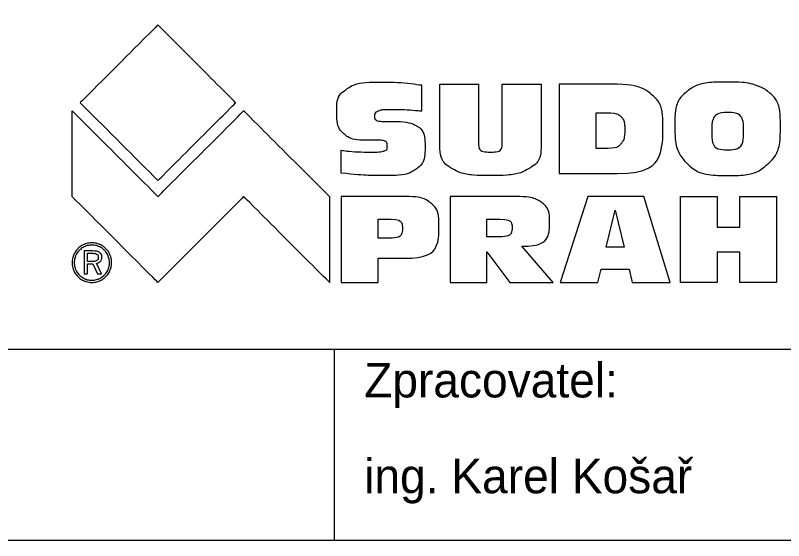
# Model space of a CAD drawing. Extents: x -78 to 132, y -2115 to -1818.
# Drawn here: x 60.19 to 102.29, y -2019.62 to -1990.83 of the extents above; entities that cross this region are included whole.
import ezdxf

# ---------------------------------------------------------------- set-up
doc = ezdxf.new("R2010")
doc.units = 0
for name, color, linetype in [('Rozpiska - logo SUDOP PRAHA', 7, 'Continuous'), ('Rozpiska_pole_6', 7, 'Continuous'), ('Rozpiska_pole_7', 7, 'Continuous')]:
    doc.layers.add(name, color=color, linetype=linetype)

msp = doc.modelspace()

# ---------------------------------------------------------------- linework, layer by layer
at = {"layer": 'Rozpiska - logo SUDOP PRAHA'}
for points in [[(92.81, -1994.604), (89.986, -1994.604), (89.986, -1999.495), (93.188, -1999.495)], [(92.634, -1998.124), (92.012, -1998.124), (92.012, -1996.176), (92.566, -1996.176)], [(81.559, -2000.764), (78.041, -2000.764), (78.041, -2005.467), (80.074, -2005.467), (80.074, -2004.146), (81.479, -2004.146)], [(87.592, -2000.764), (84.013, -2000.764), (84.013, -2005.467), (86.037, -2005.467), (86.037, -2003.8), (87.284, -2005.467), (89.656, -2005.467), (87.949, -2003.484)], [(92.109, -2005.467), (92.286, -2004.734), (93.824, -2004.734), (93.994, -2005.467), (96.076, -2005.467), (94.625, -2000.764), (91.565, -2000.764), (90.056, -2005.467), (92.109, -2005.467)], [(93.062, -2001.517), (93.552, -2003.539), (92.565, -2003.539), (93.062, -2001.517)], [(80.676, -2003.048), (80.074, -2003.048), (80.074, -2002.008), (80.778, -2002.008)], [(86.713, -2002.97), (86.037, -2002.97), (86.037, -2002.008), (86.738, -2002.008)], [(64.411, -2003.745), (63.954, -2003.745), (63.954, -2004.99), (64.142, -2004.99), (64.142, -2004.443), (64.433, -2004.443), (64.696, -2004.99), (64.91, -2004.99), (64.632, -2004.416)], [(64.375, -2004.319), (64.142, -2004.319), (64.142, -2003.872), (64.375, -2003.872)]]:
    msp.add_lwpolyline(points, dxfattribs=at)
for points in [[(63.739, -1995.621), (63.739, -1995.621), (68.001, -1991.359), (68.001, -1991.359), (68.001, -1991.359), (68.001, -1991.359), (72.263, -1995.621), (72.263, -1995.621), (72.263, -1995.621), (72.263, -1995.621), (68.001, -1999.883), (68.001, -1999.883), (68.001, -1999.883), (68.001, -1999.883), (63.739, -1995.621), (63.739, -1995.621)], [(78.041, -1999.475), (78.805, -1999.566), (79.608, -1999.612), (80.448, -1999.612), (80.448, -1999.612), (81.252, -1999.612), (81.819, -1999.494), (82.147, -1999.258), (82.147, -1999.258), (82.477, -1999.021), (82.642, -1998.613), (82.642, -1998.033), (82.642, -1998.033), (82.642, -1997.467), (82.494, -1997.088), (82.196, -1996.899), (82.196, -1996.899), (81.916, -1996.729), (81.347, -1996.644), (80.489, -1996.644), (80.489, -1996.644), (80.078, -1996.644), (79.872, -1996.548), (79.872, -1996.353), (79.872, -1996.353), (79.872, -1996.231), (79.933, -1996.142), (80.054, -1996.086), (80.054, -1996.086), (80.178, -1996.03), (80.393, -1996.002), (80.701, -1996.002), (80.701, -1996.002), (81.223, -1996.002), (81.796, -1996.032), (82.447, -1996.092), (82.447, -1996.092), (82.447, -1996.092), (82.447, -1994.65), (82.447, -1994.65), (82.447, -1994.65), (81.67, -1994.541), (80.943, -1994.486), (80.239, -1994.486), (80.239, -1994.486), (79.354, -1994.486), (78.726, -1994.612), (78.355, -1994.864), (78.355, -1994.864), (77.984, -1995.114), (77.799, -1995.514), (77.799, -1996.062), (77.799, -1996.062), (77.799, -1996.671), (77.931, -1997.093), (78.196, -1997.327), (78.196, -1997.327), (78.463, -1997.561), (78.907, -1997.676), (79.528, -1997.672), (79.528, -1997.672), (79.528, -1997.672), (80.046, -1997.672), (80.046, -1997.672), (80.046, -1997.672), (80.228, -1997.672), (80.361, -1997.692), (80.444, -1997.732), (80.444, -1997.732), (80.527, -1997.772), (80.569, -1997.859), (80.569, -1997.993), (80.569, -1997.993), (80.569, -1998.133), (80.514, -1998.224), (80.406, -1998.264), (80.406, -1998.264), (80.3, -1998.304), (80.121, -1998.324), (79.869, -1998.324), (79.869, -1998.324), (79.087, -1998.324), (78.477, -1998.29), (78.041, -1998.22), (78.041, -1998.22), (78.041, -1998.22), (78.041, -1999.475), (78.041, -1999.475)], [(83.449, -1997.93), (83.449, -1998.531), (83.669, -1998.962), (84.11, -1999.223), (84.11, -1999.223), (84.55, -1999.483), (85.248, -1999.612), (86.203, -1999.612), (86.203, -1999.612), (87.198, -1999.612), (87.912, -1999.483), (88.345, -1999.223), (88.345, -1999.223), (88.78, -1998.964), (88.998, -1998.526), (88.998, -1997.909), (88.998, -1997.909), (88.998, -1997.909), (88.998, -1994.604), (88.998, -1994.604), (88.998, -1994.604), (88.998, -1994.604), (86.871, -1994.604), (86.871, -1994.604), (86.871, -1994.604), (86.871, -1994.604), (86.871, -1997.842), (86.871, -1997.842), (86.871, -1997.842), (86.871, -1998.162), (86.658, -1998.322), (86.233, -1998.322), (86.233, -1998.322), (85.795, -1998.322), (85.576, -1998.157), (85.576, -1997.829), (85.576, -1997.829), (85.576, -1997.829), (85.576, -1994.604), (85.576, -1994.604), (85.576, -1994.604), (85.576, -1994.604), (83.449, -1994.604), (83.449, -1994.604), (83.449, -1994.604), (83.449, -1994.604), (83.449, -1997.93), (83.449, -1997.93)], [(93.188, -1999.495), (94.847, -1999.495), (95.676, -1998.629), (95.676, -1996.898), (95.676, -1996.898), (95.676, -1996.088), (95.457, -1995.503), (95.019, -1995.145), (95.019, -1995.145), (94.582, -1994.784), (93.845, -1994.604), (92.81, -1994.604)], [(101.049, -1994.774), (100.613, -1994.582), (100.012, -1994.486), (99.247, -1994.486), (99.247, -1994.486), (98.176, -1994.486), (97.423, -1994.663), (96.988, -1995.015), (96.988, -1995.015), (96.552, -1995.365), (96.334, -1995.99), (96.334, -1996.889), (96.334, -1996.889), (96.334, -1997.826), (96.556, -1998.514), (96.999, -1998.953)], [(96.999, -1998.953), (97.442, -1999.392), (98.184, -1999.612), (99.224, -1999.612), (99.224, -1999.612), (100.224, -1999.612), (100.956, -1999.401), (101.42, -1998.98), (101.42, -1998.98), (101.885, -1998.558), (102.118, -1997.861), (102.118, -1996.889), (102.118, -1996.889), (102.118, -1996.014), (101.903, -1995.395), (101.473, -1995.032), (101.473, -1995.032), (101.355, -1994.932), (101.214, -1994.846), (101.049, -1994.774)], [(63.298, -2000.764), (63.298, -2000.764), (68.001, -2005.467), (68.001, -2005.467), (68.001, -2005.467), (68.001, -2005.467), (72.703, -2000.764), (72.703, -2000.764), (72.703, -2000.764), (72.703, -2000.764), (77.406, -2005.467), (77.406, -2005.467), (77.406, -2005.467), (77.406, -2005.467), (77.406, -2000.764), (77.406, -2000.764), (77.406, -2000.764), (77.406, -2000.764), (72.703, -1996.062), (72.703, -1996.062), (72.703, -1996.062), (72.703, -1996.062), (68.001, -2000.764), (68.001, -2000.764), (68.001, -2000.764), (68.001, -2000.764), (63.298, -1996.062), (63.298, -1996.062), (63.298, -1996.062), (63.298, -1996.062), (63.298, -2000.764), (63.298, -2000.764)], [(92.566, -1996.176), (92.98, -1996.176), (93.254, -1996.245), (93.386, -1996.384), (93.386, -1996.384), (93.518, -1996.521), (93.585, -1996.754), (93.585, -1997.083), (93.585, -1997.083), (93.585, -1997.439), (93.516, -1997.702), (93.378, -1997.872), (93.378, -1997.872), (93.244, -1998.04), (92.996, -1998.124), (92.634, -1998.124)], [(99.232, -1996.152), (99.812, -1996.152), (100.102, -1996.477), (100.102, -1997.126), (100.102, -1997.126), (100.102, -1997.84), (99.812, -1998.197), (99.232, -1998.197), (99.232, -1998.197), (98.645, -1998.197), (98.351, -1997.857), (98.351, -1997.176), (98.351, -1997.176), (98.351, -1996.494), (98.645, -1996.152), (99.232, -1996.152)], [(81.479, -2004.146), (82.761, -2004.146), (83.402, -2003.569), (83.402, -2002.415), (83.402, -2002.415), (83.402, -2001.797), (83.255, -2001.367), (82.96, -2001.126), (82.96, -2001.126), (82.668, -2000.885), (82.201, -2000.764), (81.559, -2000.764)], [(87.949, -2003.484), (88.961, -2003.484), (89.468, -2003.041), (89.468, -2002.157), (89.468, -2002.157), (89.468, -2001.672), (89.325, -2001.319), (89.039, -2001.097), (89.039, -2001.097), (88.753, -2000.875), (88.271, -2000.764), (87.592, -2000.764)], [(96.64, -2005.467), (96.64, -2005.467), (98.659, -2005.467), (98.659, -2005.467), (98.659, -2005.467), (98.659, -2005.467), (98.659, -2003.804), (98.659, -2003.804), (98.659, -2003.804), (98.659, -2003.804), (99.888, -2003.804), (99.888, -2003.804), (99.888, -2003.804), (99.888, -2003.804), (99.888, -2005.467), (99.888, -2005.467), (99.888, -2005.467), (99.888, -2005.467), (101.907, -2005.467), (101.907, -2005.467), (101.907, -2005.467), (101.907, -2005.467), (101.907, -2000.764), (101.907, -2000.764), (101.907, -2000.764), (101.907, -2000.764), (99.888, -2000.764), (99.888, -2000.764), (99.888, -2000.764), (99.888, -2000.764), (99.888, -2002.437), (99.888, -2002.437), (99.888, -2002.437), (99.888, -2002.437), (98.659, -2002.437), (98.659, -2002.437), (98.659, -2002.437), (98.659, -2002.437), (98.659, -2000.764), (98.659, -2000.764), (98.659, -2000.764), (98.659, -2000.764), (96.64, -2000.764), (96.64, -2000.764), (96.64, -2000.764), (96.64, -2000.764), (96.64, -2005.467), (96.64, -2005.467)], [(80.778, -2002.008), (81.194, -2002.008), (81.402, -2002.178), (81.402, -2002.518), (81.402, -2002.518), (81.402, -2002.871), (81.16, -2003.048), (80.676, -2003.048)], [(86.738, -2002.008), (87.187, -2002.008), (87.411, -2002.155), (87.411, -2002.45), (87.411, -2002.45), (87.411, -2002.797), (87.178, -2002.97), (86.713, -2002.97)], [(64.378, -2003.304), (64.232, -2003.304), (64.093, -2003.33), (63.965, -2003.383), (63.965, -2003.383), (63.835, -2003.437), (63.721, -2003.514), (63.622, -2003.615), (63.622, -2003.615), (63.517, -2003.72), (63.437, -2003.84), (63.382, -2003.973), (63.382, -2003.973), (63.326, -2004.106), (63.298, -2004.244), (63.298, -2004.385), (63.298, -2004.385), (63.298, -2004.529), (63.325, -2004.666), (63.379, -2004.797), (63.379, -2004.797), (63.434, -2004.928), (63.512, -2005.044), (63.616, -2005.147), (63.616, -2005.147), (63.718, -2005.251), (63.835, -2005.33), (63.966, -2005.385), (63.966, -2005.385), (64.025, -2005.41), (64.085, -2005.429), (64.147, -2005.442)], [(65.343, -2004.39), (65.343, -2004.523), (65.32, -2004.645), (65.273, -2004.759), (65.273, -2004.759), (65.226, -2004.872), (65.158, -2004.973), (65.068, -2005.06), (65.068, -2005.06), (64.974, -2005.153), (64.867, -2005.223), (64.749, -2005.273), (64.749, -2005.273), (64.63, -2005.321), (64.507, -2005.346), (64.378, -2005.346), (64.378, -2005.346), (64.251, -2005.346), (64.129, -2005.322), (64.013, -2005.273), (64.013, -2005.273), (63.897, -2005.225), (63.792, -2005.155), (63.7, -2005.063), (63.7, -2005.063), (63.608, -2004.971), (63.538, -2004.867), (63.489, -2004.751), (63.489, -2004.751), (63.44, -2004.635), (63.416, -2004.514), (63.416, -2004.387), (63.416, -2004.387), (63.416, -2004.26), (63.441, -2004.138), (63.491, -2004.02), (63.491, -2004.02), (63.541, -2003.903), (63.612, -2003.797), (63.706, -2003.702), (63.706, -2003.702), (63.796, -2003.612), (63.899, -2003.542), (64.014, -2003.495), (64.014, -2003.495), (64.129, -2003.448), (64.25, -2003.425), (64.378, -2003.425), (64.378, -2003.425), (64.51, -2003.425), (64.635, -2003.449), (64.753, -2003.498), (64.753, -2003.498), (64.871, -2003.546), (64.976, -2003.616), (65.068, -2003.708), (65.068, -2003.708), (65.157, -2003.797), (65.225, -2003.9), (65.272, -2004.017), (65.272, -2004.017), (65.319, -2004.134), (65.343, -2004.258), (65.343, -2004.39)], [(64.147, -2005.442), (64.222, -2005.459), (64.299, -2005.467), (64.378, -2005.467), (64.378, -2005.467), (64.521, -2005.467), (64.659, -2005.439), (64.792, -2005.383), (64.792, -2005.383), (64.925, -2005.328), (65.044, -2005.248), (65.15, -2005.144), (65.15, -2005.144), (65.252, -2005.043), (65.33, -2004.929), (65.382, -2004.8), (65.382, -2004.8), (65.435, -2004.671), (65.461, -2004.532), (65.461, -2004.385), (65.461, -2004.385), (65.461, -2004.238), (65.435, -2004.1), (65.381, -2003.969), (65.381, -2003.969), (65.327, -2003.837), (65.25, -2003.721), (65.15, -2003.621), (65.15, -2003.621), (65.048, -2003.518), (64.932, -2003.439), (64.8, -2003.385), (64.8, -2003.385), (64.668, -2003.331), (64.528, -2003.304), (64.378, -2003.304)], [(64.632, -2004.416), (64.722, -2004.404), (64.793, -2004.368), (64.846, -2004.309), (64.846, -2004.309), (64.899, -2004.25), (64.926, -2004.177), (64.926, -2004.089), (64.926, -2004.089), (64.926, -2003.972), (64.884, -2003.885), (64.8, -2003.829), (64.8, -2003.829), (64.716, -2003.773), (64.586, -2003.745), (64.411, -2003.745)], [(64.375, -2003.872), (64.501, -2003.872), (64.592, -2003.89), (64.648, -2003.926), (64.648, -2003.926), (64.704, -2003.961), (64.733, -2004.02), (64.733, -2004.102), (64.733, -2004.102), (64.733, -2004.181), (64.706, -2004.237), (64.653, -2004.27), (64.653, -2004.27), (64.6, -2004.303), (64.507, -2004.319), (64.375, -2004.319)]]:
    msp.add_open_spline(points, degree=3, dxfattribs=at)
at = {"layer": 'Rozpiska_pole_6'}
msp.add_lwpolyline([(-59.187, -1967.118), (119.313, -1967.118), (119.313, -2019.618), (-59.187, -2019.618)], close=True, dxfattribs=at)
at = {"layer": 'Rozpiska_pole_7'}
for p, q in [((-59.187, -2009.118), (119.313, -2009.118)), ((77.68, -2019.618), (77.68, -2009.118))]:
    msp.add_line(p, q, dxfattribs=at)

# ---------------------------------------------------------------- texts
at = {"layer": 'Rozpiska_pole_6'}
for s, p in [('Zpracovatel:', (79.304, -2011.771)), ('ing. Karel Košař', (79.304, -2017.021))]:
    msp.add_text(s, height=1.89, dxfattribs=at).set_placement(p)

doc.saveas('drawing.dxf')
